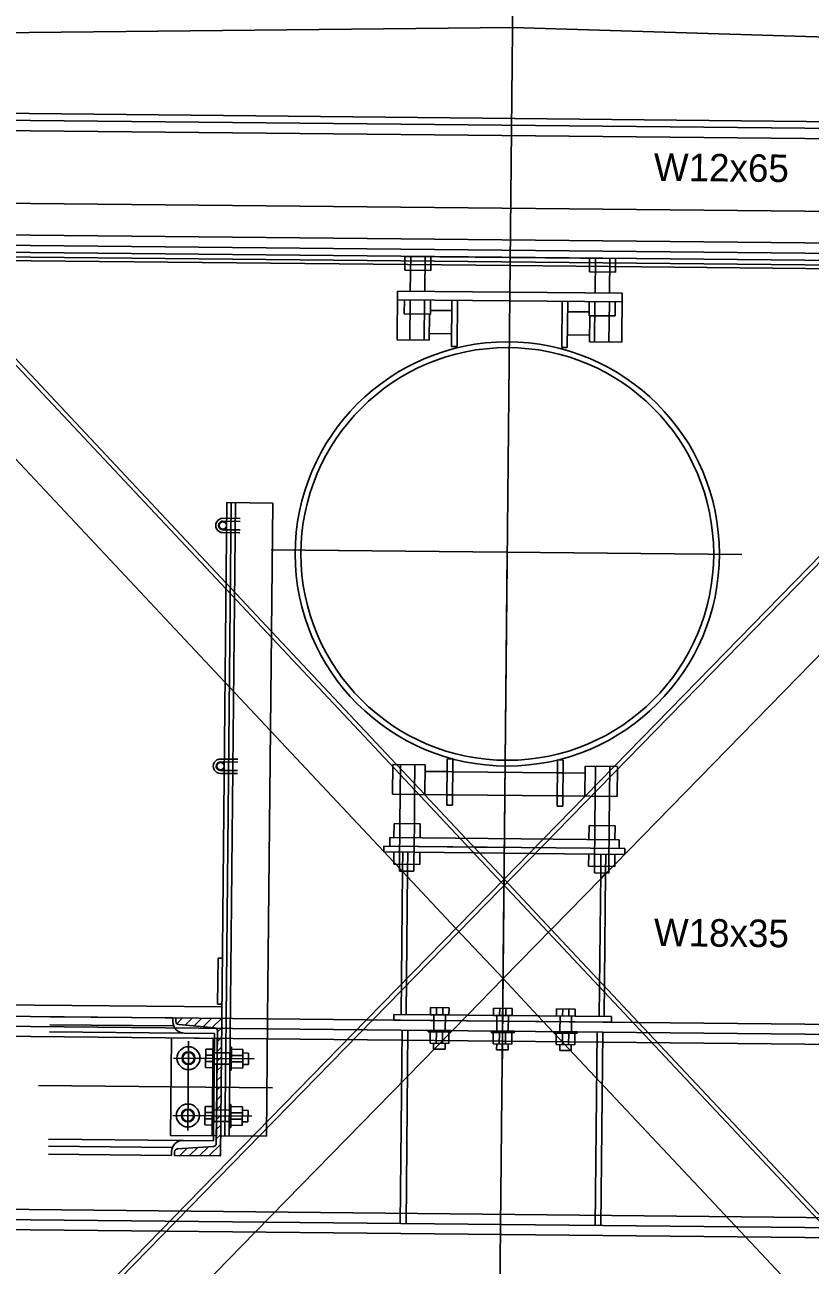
# Model space of a CAD drawing. Extents: x 632312 to 632425, y 378332 to 378413.
# Drawn here: x 632395.39 to 632401.1, y 378386.51 to 378395.52 of the extents above; entities that cross this region are included whole.
import ezdxf

# ---------------------------------------------------------------- set-up
doc = ezdxf.new("R2010")
doc.units = 0
for name, color, linetype in [('B_Boring', 7, 'Continuous'), ('B_Boring Annot', 7, 'Continuous'), ('R_Proposed Const Limits', 7, 'Continuous'), ('R_Proposed Const Limits Cut', 7, 'Continuous'), ('R_Road Edge of Shoulder', 7, 'Continuous'), ('R_Wall', 7, 'Continuous'), ('SHT_Dimensions', 7, 'Continuous')]:
    doc.layers.add(name, color=color, linetype=linetype)

msp = doc.modelspace()

# ---------------------------------------------------------------- linework, layer by layer
msp.add_line((632397.1931, 378387.7967), (632395.4914, 378387.8136))
at = {"layer": 'B_Boring'}
for p, q in [((632404.4507, 378394.7374), (632393.4096, 378394.8472)), ((632404.4512, 378394.7879), (632393.4101, 378394.8976)), ((632404.4412, 378393.7796), (632393.4001, 378393.8893)), ((632404.4417, 378393.83), (632393.4006, 378393.9398)), ((632394.3786, 378393.8192), (632398.9201, 378393.7741)), ((632398.1538, 378393.7399), (632398.1548, 378393.8421)), ((632399.6865, 378393.8248), (632398.1547, 378393.84)), ((632398.1944, 378393.5869), (632398.197, 378393.8417)), ((632398.2992, 378393.5858), (632398.3018, 378393.8406)), ((632398.3429, 378393.7381), (632398.3439, 378393.8402)), ((632398.9201, 378393.7741), (632403.4615, 378393.7289)), ((632399.4964, 378393.7266), (632399.4974, 378393.8287)), ((632399.537, 378393.5735), (632399.5396, 378393.8283)), ((632399.6418, 378393.5725), (632399.6444, 378393.8273)), ((632399.6855, 378393.7247), (632399.6865, 378393.8268)), ((632398.1538, 378393.7399), (632398.3429, 378393.7381)), ((632399.6855, 378393.7247), (632399.4964, 378393.7266)), ((632398.0984, 378393.2329), (632398.1019, 378393.5878)), ((632398.1019, 378393.5878), (632399.7343, 378393.5716)), ((632398.1013, 378393.5246), (632399.7337, 378393.5084)), ((632398.1506, 378393.422), (632398.1516, 378393.5241)), ((632398.1909, 378393.2319), (632398.1938, 378393.5237)), ((632398.2957, 378393.2309), (632398.2986, 378393.5226)), ((632398.3398, 378393.4201), (632398.3408, 378393.5222)), ((632398.4928, 378393.1848), (632398.4962, 378393.5207)), ((632398.5339, 378393.1844), (632398.5372, 378393.5203)), ((632399.2944, 378393.1769), (632399.2977, 378393.5127)), ((632399.3355, 378393.1765), (632399.3388, 378393.5123)), ((632399.4932, 378393.4086), (632399.4942, 378393.5107)), ((632399.5335, 378393.2186), (632399.5364, 378393.5103)), ((632399.6383, 378393.2176), (632399.6412, 378393.5093)), ((632399.6824, 378393.4067), (632399.6834, 378393.5089)), ((632399.7308, 378393.2166), (632399.7343, 378393.5716)), ((632398.1506, 378393.422), (632398.3398, 378393.4201)), ((632398.3344, 378393.4201), (632398.3325, 378393.2305)), ((632398.4954, 378393.4457), (632398.34, 378393.4473)), ((632399.3381, 378393.4374), (632399.4935, 378393.4358)), ((632399.6824, 378393.4067), (632399.4932, 378393.4086)), ((632399.4986, 378393.4086), (632399.4967, 378393.219)), ((632398.3325, 378393.2305), (632398.0984, 378393.2329)), ((632398.4938, 378393.2777), (632398.333, 378393.2793)), ((632399.3364, 378393.2694), (632399.4972, 378393.2678)), ((632399.4967, 378393.219), (632399.7308, 378393.2166)), ((632398.4928, 378393.1848), (632398.5339, 378393.1844)), ((632399.3355, 378393.1765), (632399.2944, 378393.1769)), ((632396.8239, 378388.3004), (632396.8611, 378392.0502)), ((632396.8551, 378388.3001), (632396.8924, 378392.0499)), ((632396.8611, 378392.0502), (632397.1945, 378392.0469)), ((632397.1572, 378388.2971), (632397.1945, 378392.0469)), ((632396.8322, 378391.9151), (632396.9572, 378391.9138)), ((632396.8324, 378391.9359), (632396.9574, 378391.9347)), ((632396.8313, 378391.8318), (632396.9563, 378391.8305)), ((632396.8315, 378391.8526), (632396.9565, 378391.8514)), ((632398.463, 378390.1869), (632398.4597, 378389.8511)), ((632398.463, 378390.1869), (632398.5041, 378390.1865)), ((632398.5041, 378390.1865), (632398.5008, 378389.8507)), ((632399.2646, 378390.1789), (632399.2613, 378389.8431)), ((632399.3057, 378390.1785), (632399.2646, 378390.1789)), ((632399.3057, 378390.1785), (632399.3023, 378389.8427)), ((632398.0677, 378390.1467), (632398.0655, 378389.9299)), ((632398.3018, 378390.1444), (632398.0677, 378390.1467)), ((632398.2996, 378389.9276), (632398.3018, 378390.1444)), ((632398.4621, 378390.094), (632398.3013, 378390.0956)), ((632399.2637, 378390.086), (632398.5032, 378390.0936)), ((632399.4655, 378390.084), (632399.3047, 378390.0856)), ((632399.4639, 378389.916), (632399.466, 378390.1328)), ((632399.466, 378390.1328), (632399.7001, 378390.1305)), ((632399.7001, 378390.1305), (632399.698, 378389.9137)), ((632398.4604, 378389.926), (632398.0655, 378389.9299)), ((632398.1211, 378389.9294), (632398.1189, 378389.7159)), ((632398.2259, 378389.9283), (632398.2237, 378389.7148)), ((632399.262, 378389.918), (632398.5015, 378389.9256)), ((632399.698, 378389.9137), (632399.3031, 378389.9176)), ((632399.5377, 378389.9153), (632399.5355, 378389.7018)), ((632399.6424, 378389.9143), (632399.6403, 378389.7008)), ((632398.4597, 378389.8511), (632398.5008, 378389.8507)), ((632399.3023, 378389.8427), (632399.2613, 378389.8431)), ((632398.0767, 378389.7163), (632398.0757, 378389.6142)), ((632398.0767, 378389.7163), (632398.2659, 378389.7144)), ((632398.2659, 378389.7144), (632398.2649, 378389.6123)), ((632399.4933, 378389.7022), (632399.4923, 378389.6001)), ((632399.6825, 378389.7003), (632399.4933, 378389.7022)), ((632398.0453, 378389.6145), (632398.0447, 378389.5513)), ((632399.7119, 378389.5979), (632398.0453, 378389.6145)), ((632399.6825, 378389.7003), (632399.6815, 378389.5982)), ((632398.0026, 378389.51), (632398.003, 378389.5517)), ((632398.003, 378389.5517), (632399.7529, 378389.5343)), ((632399.7119, 378389.5979), (632399.7113, 378389.5347)), ((632399.7525, 378389.4926), (632399.7529, 378389.5343)), ((632398.0026, 378389.51), (632399.7525, 378389.4926)), ((632398.0747, 378389.5093), (632398.0738, 378389.4213)), ((632398.2639, 378389.5074), (632398.263, 378389.4194)), ((632399.4913, 378389.4952), (632399.4904, 378389.4072)), ((632399.6805, 378389.4934), (632399.6796, 378389.4053)), ((632398.0738, 378389.4213), (632398.263, 378389.4194)), ((632398.116, 378389.4209), (632398.1155, 378389.3718)), ((632398.2203, 378389.3708), (632398.1155, 378389.3718)), ((632398.1387, 378389.3716), (632398.1284, 378388.3291)), ((632398.1742, 378389.3713), (632398.1638, 378388.3288)), ((632398.2208, 378389.4198), (632398.2203, 378389.3708)), ((632399.6796, 378389.4053), (632399.4904, 378389.4072)), ((632399.5326, 378389.4068), (632399.5321, 378389.3578)), ((632399.6369, 378389.3567), (632399.5321, 378389.3578)), ((632399.5783, 378389.3573), (632399.5679, 378388.3148)), ((632399.6137, 378389.357), (632399.6033, 378388.3144)), ((632399.6374, 378389.4057), (632399.6369, 378389.3567)), ((632396.7937, 378388.4049), (632396.797, 378388.7382)), ((632396.797, 378388.7382), (632396.8282, 378388.7379)), ((632396.8247, 378388.3837), (632394.3248, 378388.4086)), ((632396.8249, 378388.4046), (632396.7937, 378388.4049)), ((632398.3398, 378388.327), (632398.3404, 378388.3791)), ((632398.4757, 378388.3777), (632398.3404, 378388.3791)), ((632398.385, 378388.3266), (632398.3855, 378388.3786)), ((632398.4301, 378388.3261), (632398.4306, 378388.3782)), ((632398.4752, 378388.3257), (632398.4757, 378388.3777)), ((632398.7981, 378388.3225), (632398.7987, 378388.3745)), ((632398.9341, 378388.3732), (632398.7987, 378388.3745)), ((632398.8433, 378388.322), (632398.8438, 378388.3741)), ((632398.8884, 378388.3216), (632398.8889, 378388.3736)), ((632398.9335, 378388.3211), (632398.9341, 378388.3732)), ((632399.2565, 378388.3179), (632399.257, 378388.37)), ((632399.3924, 378388.3686), (632399.257, 378388.37)), ((632399.3016, 378388.3174), (632399.3021, 378388.3695)), ((632399.3467, 378388.317), (632399.3472, 378388.3691)), ((632399.3919, 378388.3165), (632399.3924, 378388.3686)), ((632404.3644, 378388.1529), (632393.365, 378388.2623)), ((632404.3652, 378388.2254), (632393.3657, 378388.3348)), ((632396.4691, 378388.3039), (632395.574, 378388.3128)), ((632396.4691, 378388.3039), (632396.4688, 378388.2769)), ((632396.4906, 378388.3037), (632396.4903, 378388.2766)), ((632396.8239, 378388.3004), (632396.4906, 378388.3037)), ((632396.4963, 378388.2618), (632396.5386, 378388.3032)), ((632396.5572, 378388.2514), (632396.6093, 378388.3025)), ((632396.6226, 378388.2456), (632396.68, 378388.3018)), ((632396.688, 378388.2397), (632396.7507, 378388.3011)), ((632396.7534, 378388.2338), (632396.8214, 378388.3004)), ((632396.8239, 378388.3004), (632396.8139, 378387.3005)), ((632398.0742, 378388.3296), (632398.0738, 378388.288)), ((632398.0738, 378388.288), (632399.657, 378388.2722)), ((632398.0742, 378388.3296), (632399.6575, 378388.3139)), ((632398.4752, 378388.3257), (632398.3398, 378388.327)), ((632398.3659, 378388.3268), (632398.3647, 378388.2126)), ((632398.4492, 378388.3259), (632398.4481, 378388.2118)), ((632398.9335, 378388.3211), (632398.7981, 378388.3225)), ((632398.8242, 378388.3222), (632398.823, 378388.208)), ((632398.9075, 378388.3214), (632398.9064, 378388.2072)), ((632399.3919, 378388.3165), (632399.2565, 378388.3179)), ((632399.2825, 378388.3176), (632399.2814, 378388.2035)), ((632399.3658, 378388.3168), (632399.3647, 378388.2026)), ((632399.6575, 378388.3139), (632399.657, 378388.2722)), ((632396.4746, 378388.2455), (632395.5734, 378388.2545)), ((632396.7715, 378388.2322), (632396.5109, 378388.2556)), ((632396.5513, 378388.1927), (632396.7711, 378388.1905)), ((632396.7634, 378387.4114), (632396.7711, 378388.1905)), ((632396.7921, 378388.2111), (632396.784, 378387.3903)), ((632396.792, 378388.2016), (632396.8232, 378388.2322)), ((632398.1356, 378388.2149), (632398.1216, 378386.8099)), ((632398.1772, 378388.2145), (632398.1633, 378386.8095)), ((632398.3231, 378388.213), (632398.323, 378388.2026)), ((632398.4896, 378388.2009), (632398.323, 378388.2026)), ((632398.4897, 378388.2113), (632398.3231, 378388.213)), ((632398.3386, 378388.2024), (632398.3378, 378388.1191)), ((632398.3837, 378388.202), (632398.3829, 378388.1187)), ((632398.4289, 378388.2015), (632398.428, 378388.1182)), ((632398.474, 378388.2011), (632398.4732, 378388.1178)), ((632398.4897, 378388.2113), (632398.4896, 378388.2009)), ((632398.7814, 378388.2084), (632398.7813, 378388.198)), ((632398.9479, 378388.1964), (632398.7813, 378388.198)), ((632398.948, 378388.2068), (632398.7814, 378388.2084)), ((632398.7969, 378388.1979), (632398.7961, 378388.1145)), ((632398.842, 378388.1974), (632398.8412, 378388.1141)), ((632398.8872, 378388.197), (632398.8863, 378388.1136)), ((632398.9323, 378388.1965), (632398.9315, 378388.1132)), ((632398.948, 378388.2068), (632398.9479, 378388.1964)), ((632399.2397, 378388.2039), (632399.2396, 378388.1935)), ((632399.4062, 378388.1918), (632399.2396, 378388.1935)), ((632399.4063, 378388.2022), (632399.2397, 378388.2039)), ((632399.2552, 378388.1933), (632399.2544, 378388.11)), ((632399.3003, 378388.1929), (632399.2995, 378388.1095)), ((632399.3455, 378388.1924), (632399.3447, 378388.1091)), ((632399.3906, 378388.192), (632399.3898, 378388.1086)), ((632399.4063, 378388.2022), (632399.4062, 378388.1918)), ((632399.5522, 378388.2008), (632399.5382, 378386.7959)), ((632399.5938, 378388.2004), (632399.5799, 378386.7954)), ((632396.4583, 378388.1582), (632396.4512, 378387.4499)), ((632396.7916, 378388.1549), (632396.4583, 378388.1582)), ((632396.7533, 378387.4469), (632396.7604, 378388.1552)), ((632396.7916, 378388.1549), (632396.7845, 378387.4466)), ((632396.7906, 378388.0602), (632396.8218, 378388.0908)), ((632396.7913, 378388.1309), (632396.8225, 378388.1615)), ((632396.8843, 378388.0915), (632396.8826, 378387.9248)), ((632396.8843, 378388.0915), (632396.8947, 378388.0914)), ((632396.8947, 378388.0914), (632396.893, 378387.9247)), ((632398.4732, 378388.1178), (632398.3378, 378388.1191)), ((632398.3638, 378388.1188), (632398.3634, 378388.0772)), ((632398.4471, 378388.118), (632398.4467, 378388.0764)), ((632398.9315, 378388.1132), (632398.7961, 378388.1145)), ((632398.8221, 378388.1143), (632398.8217, 378388.0726)), ((632398.9054, 378388.1135), (632398.905, 378388.0718)), ((632399.3898, 378388.1086), (632399.2544, 378388.11)), ((632399.2804, 378388.1097), (632399.28, 378388.0681)), ((632399.3638, 378388.1089), (632399.3633, 378388.0672)), ((632396.7075, 378388.0776), (632396.7062, 378387.9422)), ((632396.7592, 378388.0319), (632396.7071, 378388.0325)), ((632396.7596, 378388.0771), (632396.7075, 378388.0776)), ((632396.7899, 378387.9895), (632396.8211, 378388.02)), ((632396.8941, 378388.0306), (632396.9774, 378388.0298)), ((632396.8946, 378388.0757), (632396.9779, 378388.0749)), ((632396.9779, 378388.0749), (632396.9765, 378387.9395)), ((632396.9776, 378388.0489), (632397.0193, 378388.0485)), ((632397.0193, 378388.0485), (632397.0185, 378387.9651)), ((632398.4467, 378388.0764), (632398.3634, 378388.0772)), ((632398.905, 378388.0718), (632398.8217, 378388.0726)), ((632399.3633, 378388.0672), (632399.28, 378388.0681)), ((632396.7583, 378387.9417), (632396.7062, 378387.9422)), ((632396.7587, 378387.9868), (632396.7066, 378387.9873)), ((632396.7892, 378387.9188), (632396.8204, 378387.9493)), ((632396.8826, 378387.9248), (632396.893, 378387.9247)), ((632396.8932, 378387.9403), (632396.9765, 378387.9395)), ((632396.8937, 378387.9855), (632396.977, 378387.9846)), ((632396.9768, 378387.9655), (632397.0185, 378387.9651)), ((632396.7885, 378387.8481), (632396.8197, 378387.8786)), ((632396.7871, 378387.7067), (632396.8183, 378387.7372)), ((632396.7878, 378387.7774), (632396.819, 378387.8079)), ((632396.7034, 378387.6609), (632396.702, 378387.5256)), ((632396.7555, 378387.6604), (632396.7034, 378387.6609)), ((632396.7864, 378387.636), (632396.8176, 378387.6665)), ((632396.8801, 378387.6748), (632396.8785, 378387.5082)), ((632396.8801, 378387.6748), (632396.8906, 378387.6747)), ((632396.8906, 378387.6747), (632396.8889, 378387.5081)), ((632396.8904, 378387.6591), (632396.9737, 378387.6583)), ((632396.9737, 378387.6583), (632396.9724, 378387.5229)), ((632396.9735, 378387.6322), (632397.0151, 378387.6318)), ((632397.0151, 378387.6318), (632397.0143, 378387.5485)), ((632396.7546, 378387.5702), (632396.7025, 378387.5707)), ((632396.755, 378387.6153), (632396.7029, 378387.6158)), ((632396.7857, 378387.5653), (632396.8169, 378387.5958)), ((632396.8895, 378387.5688), (632396.9728, 378387.568)), ((632396.89, 378387.614), (632396.9733, 378387.6131)), ((632396.9727, 378387.5489), (632397.0143, 378387.5485)), ((632396.4512, 378387.4499), (632396.7846, 378387.4466)), ((632396.7541, 378387.525), (632396.702, 378387.5256)), ((632396.7843, 378387.4239), (632396.8155, 378387.4544)), ((632396.785, 378387.4946), (632396.8162, 378387.5251)), ((632396.8785, 378387.5082), (632396.8889, 378387.5081)), ((632396.8891, 378387.5237), (632396.9724, 378387.5229)), ((632396.4658, 378387.3623), (632395.5646, 378387.3712)), ((632396.763, 378387.3697), (632396.5019, 378387.3515)), ((632396.5436, 378387.4136), (632396.7634, 378387.4114)), ((632396.5893, 378387.3027), (632396.6496, 378387.3618)), ((632396.66, 378387.302), (632396.7265, 378387.3672)), ((632396.7307, 378387.3013), (632396.8147, 378387.3837)), ((632396.4592, 378387.304), (632395.564, 378387.3129)), ((632396.4592, 378387.304), (632396.4594, 378387.3311)), ((632396.4806, 378387.3038), (632396.4809, 378387.3309)), ((632396.8139, 378387.3005), (632396.4806, 378387.3038)), ((632396.8139, 378387.3005), (632396.4806, 378387.3038)), ((632396.4821, 378387.3376), (632396.4951, 378387.3504)), ((632396.5186, 378387.3034), (632396.5727, 378387.3564)), ((632396.8014, 378387.3006), (632396.814, 378387.313)), ((632396.8108, 378387.3005), (632396.814, 378387.3036)), ((632404.3505, 378386.748), (632393.351, 378386.8574)), ((632404.3497, 378386.6755), (632393.3503, 378386.7849))]:
    msp.add_line(p, q, dxfattribs=at)
for points in [[(632396.8481, 378390.7422), (632394.3742, 378393.378), (632394.7388, 378393.7202), (632396.8553, 378391.4652)], [(632399.6797, 378389.4202), (632403.4571, 378393.2877), (632403.0994, 378393.6371), (632399.6748, 378390.1308)], [(632397.1852, 378391.1137), (632398.093, 378390.1465)], [(632398.074, 378389.4362), (632397.178, 378390.3908)], [(632398.2984, 378389.9276), (632398.5975, 378389.609)], [(632399.4651, 378389.916), (632399.1598, 378389.6034)], [(632399.0583, 378389.4995), (632398.8757, 378389.3126), (632397.8769, 378388.2899)], [(632398.6968, 378389.5031), (632398.8757, 378389.3126)], [(632398.1157, 378389.3917), (632398.0881, 378389.4211)], [(632398.1387, 378389.3672), (632398.1345, 378389.3717)], [(632399.6136, 378389.3525), (632399.6179, 378389.3569)], [(632399.6371, 378389.3766), (632399.6653, 378389.4055)], [(632398.526, 378388.9545), (632398.1737, 378389.3298)], [(632398.6094, 378388.3243), (632398.8685, 378388.5896), (632399.5778, 378389.3159)], [(632399.2182, 378388.9476), (632399.8539, 378388.2703)], [(632399.1223, 378388.3192), (632398.8685, 378388.5896)], [(632396.3775, 378386.7548), (632394.2871, 378384.6144)], [(632394.6448, 378384.2651), (632397.0697, 378386.7479)], [(632403.0054, 378384.182), (632400.6303, 378386.7125)]]:
    msp.add_lwpolyline(points, dxfattribs=at)
for centre, radius in [((632398.8992, 378391.6767), 1.5417), ((632398.8992, 378391.6767), 1.5), ((632396.5818, 378388.0111), 0.0469), ((632396.5777, 378387.5945), 0.0469)]:
    msp.add_circle(centre, radius, dxfattribs=at)
for centre, radius, start, end in [((632396.8319, 378391.8838), 0.0521, 89.43036, 269.43036), ((632396.8319, 378391.8838), 0.0312, 89.43036, 269.43036), ((632396.5522, 378388.276), 0.0833, 179.43036, 269.43036), ((632396.5111, 378388.2764), 0.0208, 179.4219, 269.43036), ((632396.7713, 378388.2114), 0.0208, 359.43036, 89.43036), ((632396.5428, 378387.3302), 0.0833, 89.43036, 179.43036), ((632396.7632, 378387.3905), 0.0208, 269.43036, 359.43036), ((632396.5017, 378387.3307), 0.0208, 89.43036, 179.43036)]:
    msp.add_arc(centre, radius, start, end, dxfattribs=at)
at = {"layer": 'B_Boring Annot'}
for q in [(632394.9783, 378395.4633), (632402.8946, 378395.3846)]:
    msp.add_line((632398.9372, 378395.5031), q, dxfattribs=at)
at = {"layer": 'R_Proposed Const Limits'}
msp.add_line((632396.7693, 378388.0093), (632396.7652, 378387.5926), dxfattribs=at)
msp.add_arc((632396.5522, 378388.276), 0.0833, 179.43036, 269.43036, dxfattribs=at)
at = {"layer": 'R_Proposed Const Limits Cut'}
for p, q in [((632404.45, 378394.6629), (632393.4089, 378394.7726)), ((632403.4656, 378394.1456), (632394.3828, 378394.2359)), ((632404.4425, 378393.9046), (632393.4013, 378394.0143)), ((632403.4618, 378393.755), (632394.3789, 378393.8453)), ((632394.716, 378393.6988), (632403.3472, 378384.5027)), ((632403.1218, 378393.6153), (632394.3094, 378384.5926)), ((632396.8779, 378387.4457), (632396.9236, 378392.0496)), ((632396.8553, 378391.4652), (632397.1852, 378391.1137)), ((632396.8481, 378390.7422), (632397.178, 378390.3908)), ((632398.2996, 378389.9276), (632398.093, 378390.1465)), ((632398.1211, 378389.9294), (632398.1232, 378390.1462)), ((632398.2259, 378389.9283), (632398.228, 378390.1451)), ((632398.4621, 378390.094), (632398.5032, 378390.0936)), ((632399.2637, 378390.086), (632399.3047, 378390.0856)), ((632399.4651, 378389.916), (632399.6748, 378390.1308)), ((632399.5377, 378389.9153), (632399.5398, 378390.1321)), ((632399.6424, 378389.9143), (632399.6446, 378390.1311)), ((632398.4604, 378389.926), (632398.5015, 378389.9256)), ((632399.262, 378389.918), (632399.3031, 378389.9176)), ((632398.1189, 378389.7159), (632398.116, 378389.4209)), ((632398.2237, 378389.7148), (632398.2208, 378389.4198)), ((632399.5355, 378389.7018), (632399.5326, 378389.4068)), ((632399.6374, 378389.4057), (632399.6403, 378389.7008)), ((632398.6968, 378389.5031), (632398.5975, 378389.609)), ((632399.0583, 378389.4995), (632399.1598, 378389.6034)), ((632398.074, 378389.4362), (632398.0881, 378389.4211)), ((632398.1387, 378389.3716), (632398.1401, 378389.5087)), ((632398.1742, 378389.3713), (632398.1755, 378389.5083)), ((632399.5783, 378389.3573), (632399.5796, 378389.4944)), ((632399.6137, 378389.357), (632399.615, 378389.494)), ((632398.1157, 378389.3917), (632398.1345, 378389.3717)), ((632398.1387, 378389.3672), (632398.1737, 378389.3298)), ((632399.5778, 378389.3159), (632399.6136, 378389.3525)), ((632399.6179, 378389.3569), (632399.6371, 378389.3766)), ((632399.6653, 378389.4055), (632399.6797, 378389.4202)), ((632399.2182, 378388.9476), (632398.8757, 378389.3126)), ((632398.526, 378388.9545), (632398.8685, 378388.5896)), ((632397.8769, 378388.2899), (632396.3775, 378386.7548)), ((632396.8551, 378388.3001), (632396.8466, 378387.446)), ((632397.0697, 378386.7479), (632398.6094, 378388.3243)), ((632397.1572, 378388.2971), (632397.1487, 378387.443)), ((632399.1223, 378388.3192), (632400.6303, 378386.7125)), ((632399.8539, 378388.2703), (632401.3225, 378386.7056)), ((632404.3637, 378388.0796), (632393.3643, 378388.189)), ((632396.5383, 378388.1939), (632395.5729, 378388.2035)), ((632396.7593, 378388.051), (632396.8839, 378388.0498)), ((632396.7585, 378387.9677), (632396.883, 378387.9665)), ((632396.7552, 378387.6344), (632396.8797, 378387.6332)), ((632396.7544, 378387.5511), (632396.8789, 378387.5498)), ((632396.5305, 378387.4127), (632395.5651, 378387.4223)), ((632397.1487, 378387.443), (632396.8154, 378387.4463)), ((632404.3512, 378386.8213), (632393.3517, 378386.9307))]:
    msp.add_line(p, q, dxfattribs=at)
for centre, radius in [((632396.5818, 378388.0111), 0.0833), ((632396.5818, 378388.0111), 0.0417), ((632396.5777, 378387.5945), 0.0833), ((632396.5777, 378387.5945), 0.0417)]:
    msp.add_circle(centre, radius, dxfattribs=at)
at = {"layer": 'R_Road Edge of Shoulder'}
msp.add_line((632398.7691, 378378.5906), (632399.0996, 378411.8322), dxfattribs=at)
at = {"layer": 'R_Wall'}
for p, q in [((632396.583, 378388.1339), (632396.5766, 378387.4858)), ((632396.4725, 378388.0122), (632397.0584, 378388.0064)), ((632396.4694, 378387.5956), (632397.0421, 378387.5899))]:
    msp.add_line(p, q, dxfattribs=at)
at = {"layer": 'SHT_Dimensions'}
for p, q in [((632397.1836, 378391.7058), (632400.6041, 378391.6718)), ((632398.8993, 378391.6887), (632398.8614, 378387.8771)), ((632396.8148, 378390.1652), (632396.9398, 378390.1639)), ((632396.815, 378390.186), (632396.94, 378390.1848)), ((632396.8139, 378390.0818), (632396.9389, 378390.0806)), ((632396.8141, 378390.1027), (632396.9391, 378390.1014)), ((632398.878, 378389.543), (632398.0447, 378389.5513)), ((632396.7596, 378388.0771), (632396.7583, 378387.9417)), ((632396.7555, 378387.6604), (632396.7541, 378387.525))]:
    msp.add_line(p, q, dxfattribs=at)
for centre in [(632396.8319, 378391.8838), (632396.8145, 378390.1339)]:
    msp.add_circle(centre, 0.0261, dxfattribs=at)
for radius in [0.0521, 0.0312]:
    msp.add_arc((632396.8145, 378390.1339), radius, 89.43036, 269.43036, dxfattribs=at)

# ---------------------------------------------------------------- texts
for s, p in [('W12x65', (632399.9637, 378394.3895)), ('W18x35', (632399.964, 378388.8264))]:
    msp.add_text(s, height=0.2, rotation=359.43036, dxfattribs=at).set_placement(p)

doc.saveas('drawing.dxf')
